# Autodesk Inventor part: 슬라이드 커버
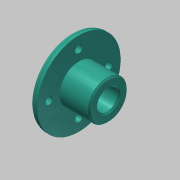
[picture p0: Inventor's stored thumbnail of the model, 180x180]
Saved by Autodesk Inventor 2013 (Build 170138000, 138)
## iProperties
Created: 2015-12
Part Number: 슬라이드 커버
Document SubType Name: Modeling
Designer: mdu
Density: 2.71 g/cm^3
Material: 알루미늄 6061
Mass: 49.5251 g
Surface Area: 80.5945 cm^2
Volume: 18.2749 cm^3
Author: mdu
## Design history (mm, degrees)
sketch "스케치1"
  geometry: L1 (-12.5, 0)-(12.5, 0); L2 (-12.5, 0)-(-12.5, 28); L3 (-12.5, 28)-(-7.5, 28); L4 (-7.5, 28)-(-7.5, 13); L5 (-7.5, 13)-(12.5, 13); L6 (12.5, 13)-(12.5, 0); 2 further points
  constraints: 12 end point, 3 perpendicular, 1 coincident, 1 horizontal, 1 midpoint, 1 parallel
  dimensions: "d1" = 56 diameter of L3 L1; "d2" = 26 diameter of L5 L1; "d5" = 5 distance of L2.end L3.end; "d32" = 20 distance of L4.end L5.end
revolve "회전1" sketch "스케치1" stored, may be unused: angle "d6" = 90 deg
sketch "스케치2" dims "d33" = 40
  geometry: 3 further points
  constraints: 2 vertical alignment, 1 coincident, 2 other
hole "구멍1" sketch "스케치2" at (0, 20) diameter "d8" = 5; stored, may be unused: countersink angle "d12" = 90 deg, drill point angle "d14" = 118 deg; dims "d9" = 6, "d10" = 8, "d11" = 4.4, "d13" = 8
hole "구멍2" diameter "d20" = 14; stored, may be unused: countersink angle "d24" = 90 deg, drill point angle "d26" = 0 deg; dims "d18" = 10, "d19" = 10, "d21" = 6, "d22" = 8, "d23" = 4.4, "d25" = 8
fillet "모깎기1" dims "d27" = 3
chamfer "모따기1" distance "d29" = 1; stored, may be unused: second distance "d30" = 2, angle "d31" = 45 deg
node "솔리드1"
pattern_circular "원형 패턴1" dims angle "d16" = 360 deg
